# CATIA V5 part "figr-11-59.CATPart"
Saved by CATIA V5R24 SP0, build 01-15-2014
Part number: Part1
Bounding box of the stored display mesh (mm): x -59.829 to 59.829, y -71.429 to 72.174, z -61 to 76
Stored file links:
  D:\KAVITA\CATIA V5-6R2014 Project_ Kavita\CATIA V5-6R2014_partfiles\Partfiles\c11_catia_v5-6r2014_prt\figr-11-59.CATPart
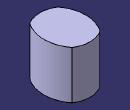
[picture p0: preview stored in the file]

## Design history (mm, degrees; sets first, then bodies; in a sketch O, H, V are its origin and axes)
Set1
  Extrude1: Element1 Sketch1, Lim1 76, Lim2 61, Direction xy-plane
Body1 (main body)
  Sketch1 on xy-plane, origin (0, 0, 0), H (0, 1, 0), V (-1, 0, 0)
    arc A1 centre (0, -40) radius 100 from (-60, 40) to (60, 40) cw
    point P2 (0, 60)
    point P3 (-60, 40)
    point P4 (60, 40)
    axis line L1 (-90, 0) -> (80, 0)
    point P6 (80, 0)
    point P7 (60, -40)
    point P8 (-60, -40)
    arc A2 centre (0, 40) radius 100 from (-60, -40) to (60, -40) ccw
    arc A3 centre (4.2857, 0) radius 75.7143 from (-60, 40) to (-60, -40) ccw
    arc A4 centre (0.3727, 0) radius 71.8012 from (60, -40) to (60, 40) ccw
    coincidence: A1 P2, P2 V, A3 P6
    horizontal: L1 H
    symmetry: P4 P7 L1, P3 P8 L1, A1 A2 L1
    tangency: A4 A3
  Sketch2 on xy-plane, origin (0, 0, 0), H (1, 0, 0), V (0, 1, 0)
    spline S1 through (80, 90) (60, 60) (70, 0) (50, -50) (50, -80)
    point P1 (70, 0)
    coincidence: P1 H
  CloseSurface1: CloseElement Extrude1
